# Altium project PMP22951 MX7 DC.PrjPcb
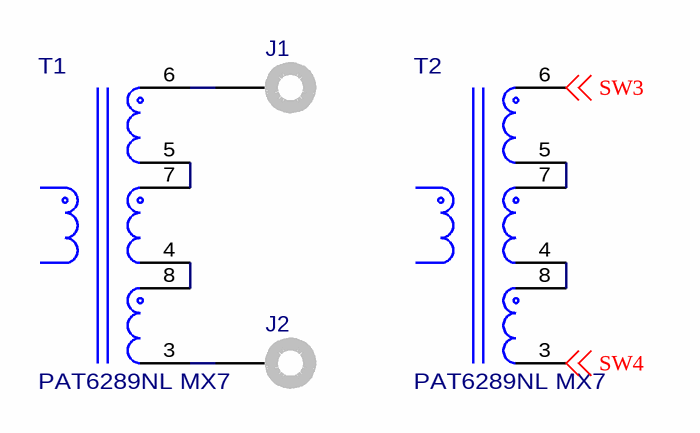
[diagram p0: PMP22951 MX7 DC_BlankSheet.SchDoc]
CopyrightYear: 2024; PCB_Layout: B Lough; PCB_Rev: A; PRJ_Customer: Public Release; PRJ_Engineer: B Lough; PRJ_Number: PMP22951 MX7 DC; PRJ_Title: PMP22951 MX7 DC; SCH_Rev: A; TechSupport: http://www.ti.com/support; TID: N/A
1 sheet, 4 parts. Net scope: global (net labels, ports and power ports of the same name join across sheets).
Board file: PMP22951 MX7 DC.PcbDoc

## Sheet PMP22951 MX7 DC_BlankSheet.SchDoc
size 431 x 279 mm; Date: Not shown in title block; ApprovedBy: Not shown in title block; CheckedBy: Not shown in title block; Author: Not shown in title block; CompanyName: Not shown in title block; Engineer: Not shown in title block; Organization: Not shown in title block; Address1: Not shown in title block; Address2: Not shown in title block; Address3: Not shown in title block; Address4: Not shown in title block; DocumentNumber: 2; Revision: Use project parameter SCH_Rev; SheetNumber: 1; SheetTotal: 1; PageSetup: Record=PageOptions¦CenterHorizontal=True¦CenterVertical=True¦PrintScale=1.00¦XCorrection=1.00¦YCorrection=1.00¦PrintKind=0¦BorderSize=5000000¦LeftOffset=0¦BottomOffset=0¦Orientation=2¦PaperLength=1000¦PaperWidth=1000¦Scale=100¦PaperSource=15¦PrintQuality=600¦MediaType=1¦DitherType=10¦PaperKind=Letter¦PrintScaleMode=1

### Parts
J1  575-4  [Keystone_575-4]  (value not drawn)
J2  575-4  [Keystone_575-4]  (value not drawn)
T1  PAT6289NL MX7  [FP-PAT6289NL MX7_PTH8_46MM5_27MM0-MFG]
T2  PAT6289NL MX7  [FP-PAT6289NL MX7_PTH8_46MM5_27MM0-MFG]

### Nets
SW3: T2.6 ; off-sheet SW3
SW4: T2.3 ; off-sheet SW4
NetJ1_1: J1.1 T1.6
NetJ2_1: J2.1 T1.3
NetT1_4: T1.4 T1.8
NetT1_5: T1.5 T1.7
NetT2_4: T2.4 T2.8
NetT2_5: T2.5 T2.7

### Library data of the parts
J1 J2 = CMP-0055165-2: Standard Banana Jack, Uninsulated, 5.5mm; Manufacturer: Keystone; CT: TRUE; Green_REACh: Passed; CNHeader: FALSE; Green_Lifecycle: Active
T1 T2 = CMP-0120260-1: Transformer PSFB 2.7kW EW45 TH; Manufacturer: Pulse; DCR_ohm: 37m; Ind_H: 565µH; Ns1toNp: 16:1; Rsec1_ohm: 380µ; SizeZ_mm: 32.5mm; AEC Qualified: No; Frequency_Fixed: 140-200kHz; Voltage_Isolation_Vrms: 3kV

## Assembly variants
001: not fitted J1 J2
